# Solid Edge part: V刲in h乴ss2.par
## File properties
Author: Türk
Template: Iso Part.par
Last saved by: Türk
Revision: 12
Application: Solid Edge
Accuracy: 0,990
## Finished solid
Body 1: sheet body, 2 faces, 20 edges, 20 vertices.
  Faces by surface: plane 2
  Edges by curve: line 20
Body 2: solid body, 10 faces, 10 edges, 0 vertices.
  Faces by surface: cylinder 4, plane 4, cone 2
  Edges by curve: circle 10
Bounding box of the edges (mm): 50.000 x 65.000 x 65.000, from (0, -32.5, -32.5) to (50, 32.5, 32.5).
Cylindrical faces by radius (mm): R27.5 x2, R30 x1, R32.5 x1
Conical faces (half-angle, radius in mm at the cone's reference point): 45 deg R31.5 x1, 45 deg R32.5 x1
Planar faces by outward normal: +x 2, -x 2
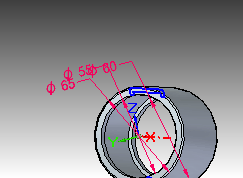
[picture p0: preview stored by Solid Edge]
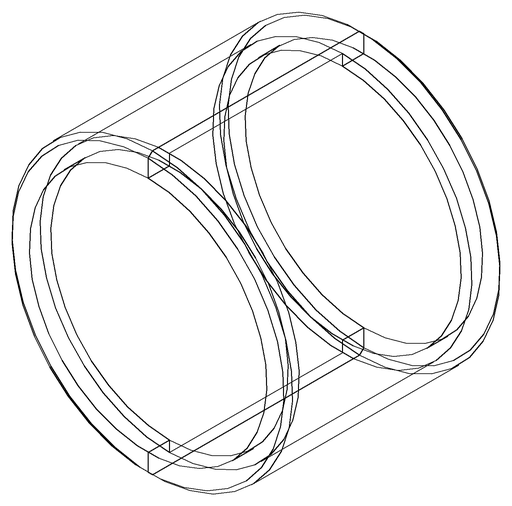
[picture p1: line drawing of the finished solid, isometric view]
